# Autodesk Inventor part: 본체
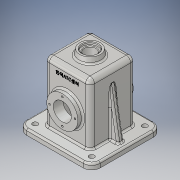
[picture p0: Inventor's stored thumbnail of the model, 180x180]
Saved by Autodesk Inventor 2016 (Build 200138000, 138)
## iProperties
Created: 2022-11
Part Number: 본체
Material: 알루미늄 6061
Document SubType Name: Modeling
Designer: CAD03
Density: 2.7 g/cm^3
Appearance: 알루미늄 - 평지
Mass: 1130.08 g
Surface Area: 1016.68 cm^2
Volume: 418.546 cm^3
Author: CAD03
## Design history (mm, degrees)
node "작업 평면1"
sketch "스케치1"
  geometry: L1 (-40, 40)-(40, 40); L2 (40, 40)-(40, -40); L3 (40, -40)-(-40, -40); L4 (-40, -40)-(-40, 40); L5 (-40, 40)-(40, -40); L6 (40, 40)-(-40, -40); 1 further point
  constraints: 12 end point, 2 midpoint, 2 parallel, 1 horizontal, 1 perpendicular
  dimensions: "d1" = 80 distance of L2.end L3.end; "d2" = 80 distance of L1.end L2.end
extrude "돌출1" new body sketch "스케치1" distance "d3" = 117; taper "d4" = 0 deg
fillet "모깎기1" dims "d5" = 8
fillet "모깎기2" dims "d6" = 8
feature "쉘1" dims "d7" = 8
fillet "모깎기3" dims "d8" = 3
fillet "모깎기4" dims "d9" = 3
sketch "스케치2"
  geometry: L1 (-65, 62)-(65, 62); L2 (65, 62)-(65, -62); L3 (65, -62)-(-65, -62); L4 (-65, -62)-(-65, 62); L5 (-65, 62)-(65, -62); L6 (65, 62)-(-65, -62); L7 (-29, -32)-(29, -32) reference; L8 (32, -29)-(32, 29) reference; L9 (29, 32)-(-29, 32) reference; L10 (-32, 29)-(-32, -29) reference; L11 (32, -40)-(-32, -40) reference; L12 (-40, -32)-(-40, 32) reference; L13 (-32, 40)-(32, 40) reference; L14 (40, 32)-(40, -32) reference; A1 r 3 centre (29, -29) between (29, -32) and (32, -29) reference; A2 r 3 centre (29, 29) between (32, 29) and (29, 32) reference; A3 r 3 centre (-29, 29) between (-29, 32) and (-32, 29) reference; A4 r 3 centre (-29, -29) between (-32, -29) and (-29, -32) reference; A5 r 8 centre (32, -32) between (32, -40) and (40, -32) reference; A6 r 8 centre (-32, -32) between (-40, -32) and (-32, -40) reference; A7 r 8 centre (-32, 32) between (-32, 40) and (-40, 32) reference; A8 r 8 centre (32, 32) between (40, 32) and (32, 40) reference; 1 further point
  constraints: 12 end point, 2 midpoint, 2 parallel, 1 horizontal, 1 perpendicular
  dimensions: "d10" = 130 distance of L2.end L3.end; "d11" = 124 distance of L1.end L2.end
extrude "돌출3" join sketch "스케치2" distance "d16" = 10; taper "d17" = 0 deg
fillet "모깎기7" dims "d18" = 15
hole "구멍1" diameter "d21" = 9; stored, may be unused: countersink angle "d25" = 90 deg, drill point angle "d27" = 0 deg; dims "d19" = 10, "d20" = 10, "d22" = 6, "d23" = 4, "d24" = 2, "d26" = 8
fillet "모깎기8" dims "d34" = 3
sketch "스케치3"
  geometry: L1 (82, -109)-(-18, -109) reference; C1 r 27.5 at (32, -54); 1 further point
  constraints: 1 centre point, 1 coincident
  dimensions: "d37" = 55 diameter of C1; "d38" = 55 distance from line of L1 C1.centre
extrude "돌출4" join sketch "스케치3" distance "d39" = 9; taper "d40" = 0 deg
hole "구멍2" diameter "d43" = 32; stored, may be unused: countersink angle "d47" = 90 deg, drill point angle "d49" = 0 deg; dims "d41" = 10, "d42" = 10, "d44" = 6, "d45" = 4, "d46" = 2, "d48" = 8
fillet "모깎기9" dims "d50" = 3
sketch "스케치4"
  geometry: L1 (0, 0)-(0, 22.5)
  constraints: 2 end point, 1 vertical
  dimensions: "d51" = 22.5 distance of L1.start L1.end
hole "구멍3" sketch "스케치4" at (0, 22.5) diameter "d52" = 3.242; stored, may be unused: countersink angle "d56" = 90 deg, drill point angle "d58" = 118 deg; dims "d53" = 8, "d54" = 4, "d55" = 2, "d57" = 10
sketch "스케치5"
  geometry: L1 (65, -55)-(65, -48) reference; L2 (50, -45)-(62, -45) reference; L3 (-55, -45)-(-40, 40.069); L4 (-62, -45)-(-50, -45) reference; L5 (-65, -48)-(-65, -55) reference; L6 (-40, 54)-(-40, -45) reference; 1 further point
  constraints: 2 end point, 2 point on line
  dimensions: "d64" = 100 deg angle of L4 L3; "d65" = 10 distance from line of L5 L3.start
feature "리브1" sketch "스케치5" dims "d66" = 1, "d67" = 10, "d68" = 0, "d69" = 0, "d70" = 1, "d71" = 1
fillet "모깎기10" dims "d72" = 3
fillet "모깎기11" dims "d73" = 3
fillet "모깎기12" dims "d74" = 3
sketch "스케치6"
  geometry: C1 r 20 at (0, 0); 1 further point
  constraints: 1 centre point, 1 coincident
  dimensions: "d76" = 40 diameter of C1
extrude "돌출5" join sketch "스케치6" distance "d77" = 10; taper "d78" = -10 deg
fillet "모깎기13" dims "d79" = 3
hole "구멍4" diameter "d82" = 21; stored, may be unused: countersink angle "d86" = 90 deg, drill point angle "d88" = 0 deg; dims "d80" = 10, "d81" = 10, "d83" = 8, "d84" = 28, "d85" = 4, "d87" = 10
chamfer "모따기1" distance "d89" = 1; stored, may be unused: second distance "d90" = 2, angle "d91" = 45 deg
node "작업 평면3"
sketch "스케치7"
  geometry: L1 (-18.237, 72)-(18.237, 72) reference; L2 (40, -42)-(40, 54) reference; 2 further points
  constraints: 1 other
  dimensions: "d93" = 25 distance from line of point (0, 47) L1; "d94" = 40 distance from line of L2 point (0, 47)
feature "엠보싱1" sketch "스케치7" dims "d7" = 8, "d95" = 0.5, "d96" = 0
feature "분할1"
node "솔리드1"
pattern_linear "직사각형 패턴1" dims "d30" = 100, "d33" = 94
mirror "대칭1"
pattern_circular "원형 패턴1" dims angle "d60" = 360 deg
mirror "대칭2"
mirror "대칭3"
node "투영된 루프1"
other parameters: "d0" = -55
